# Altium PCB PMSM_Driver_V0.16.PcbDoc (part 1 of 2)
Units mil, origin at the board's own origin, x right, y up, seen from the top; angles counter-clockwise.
Board outline 3933.5 x 3936.3 mil, 2 copper layers (Top Layer, Bottom Layer); 174 components, 117 nets, 508 pads, 484 vias.
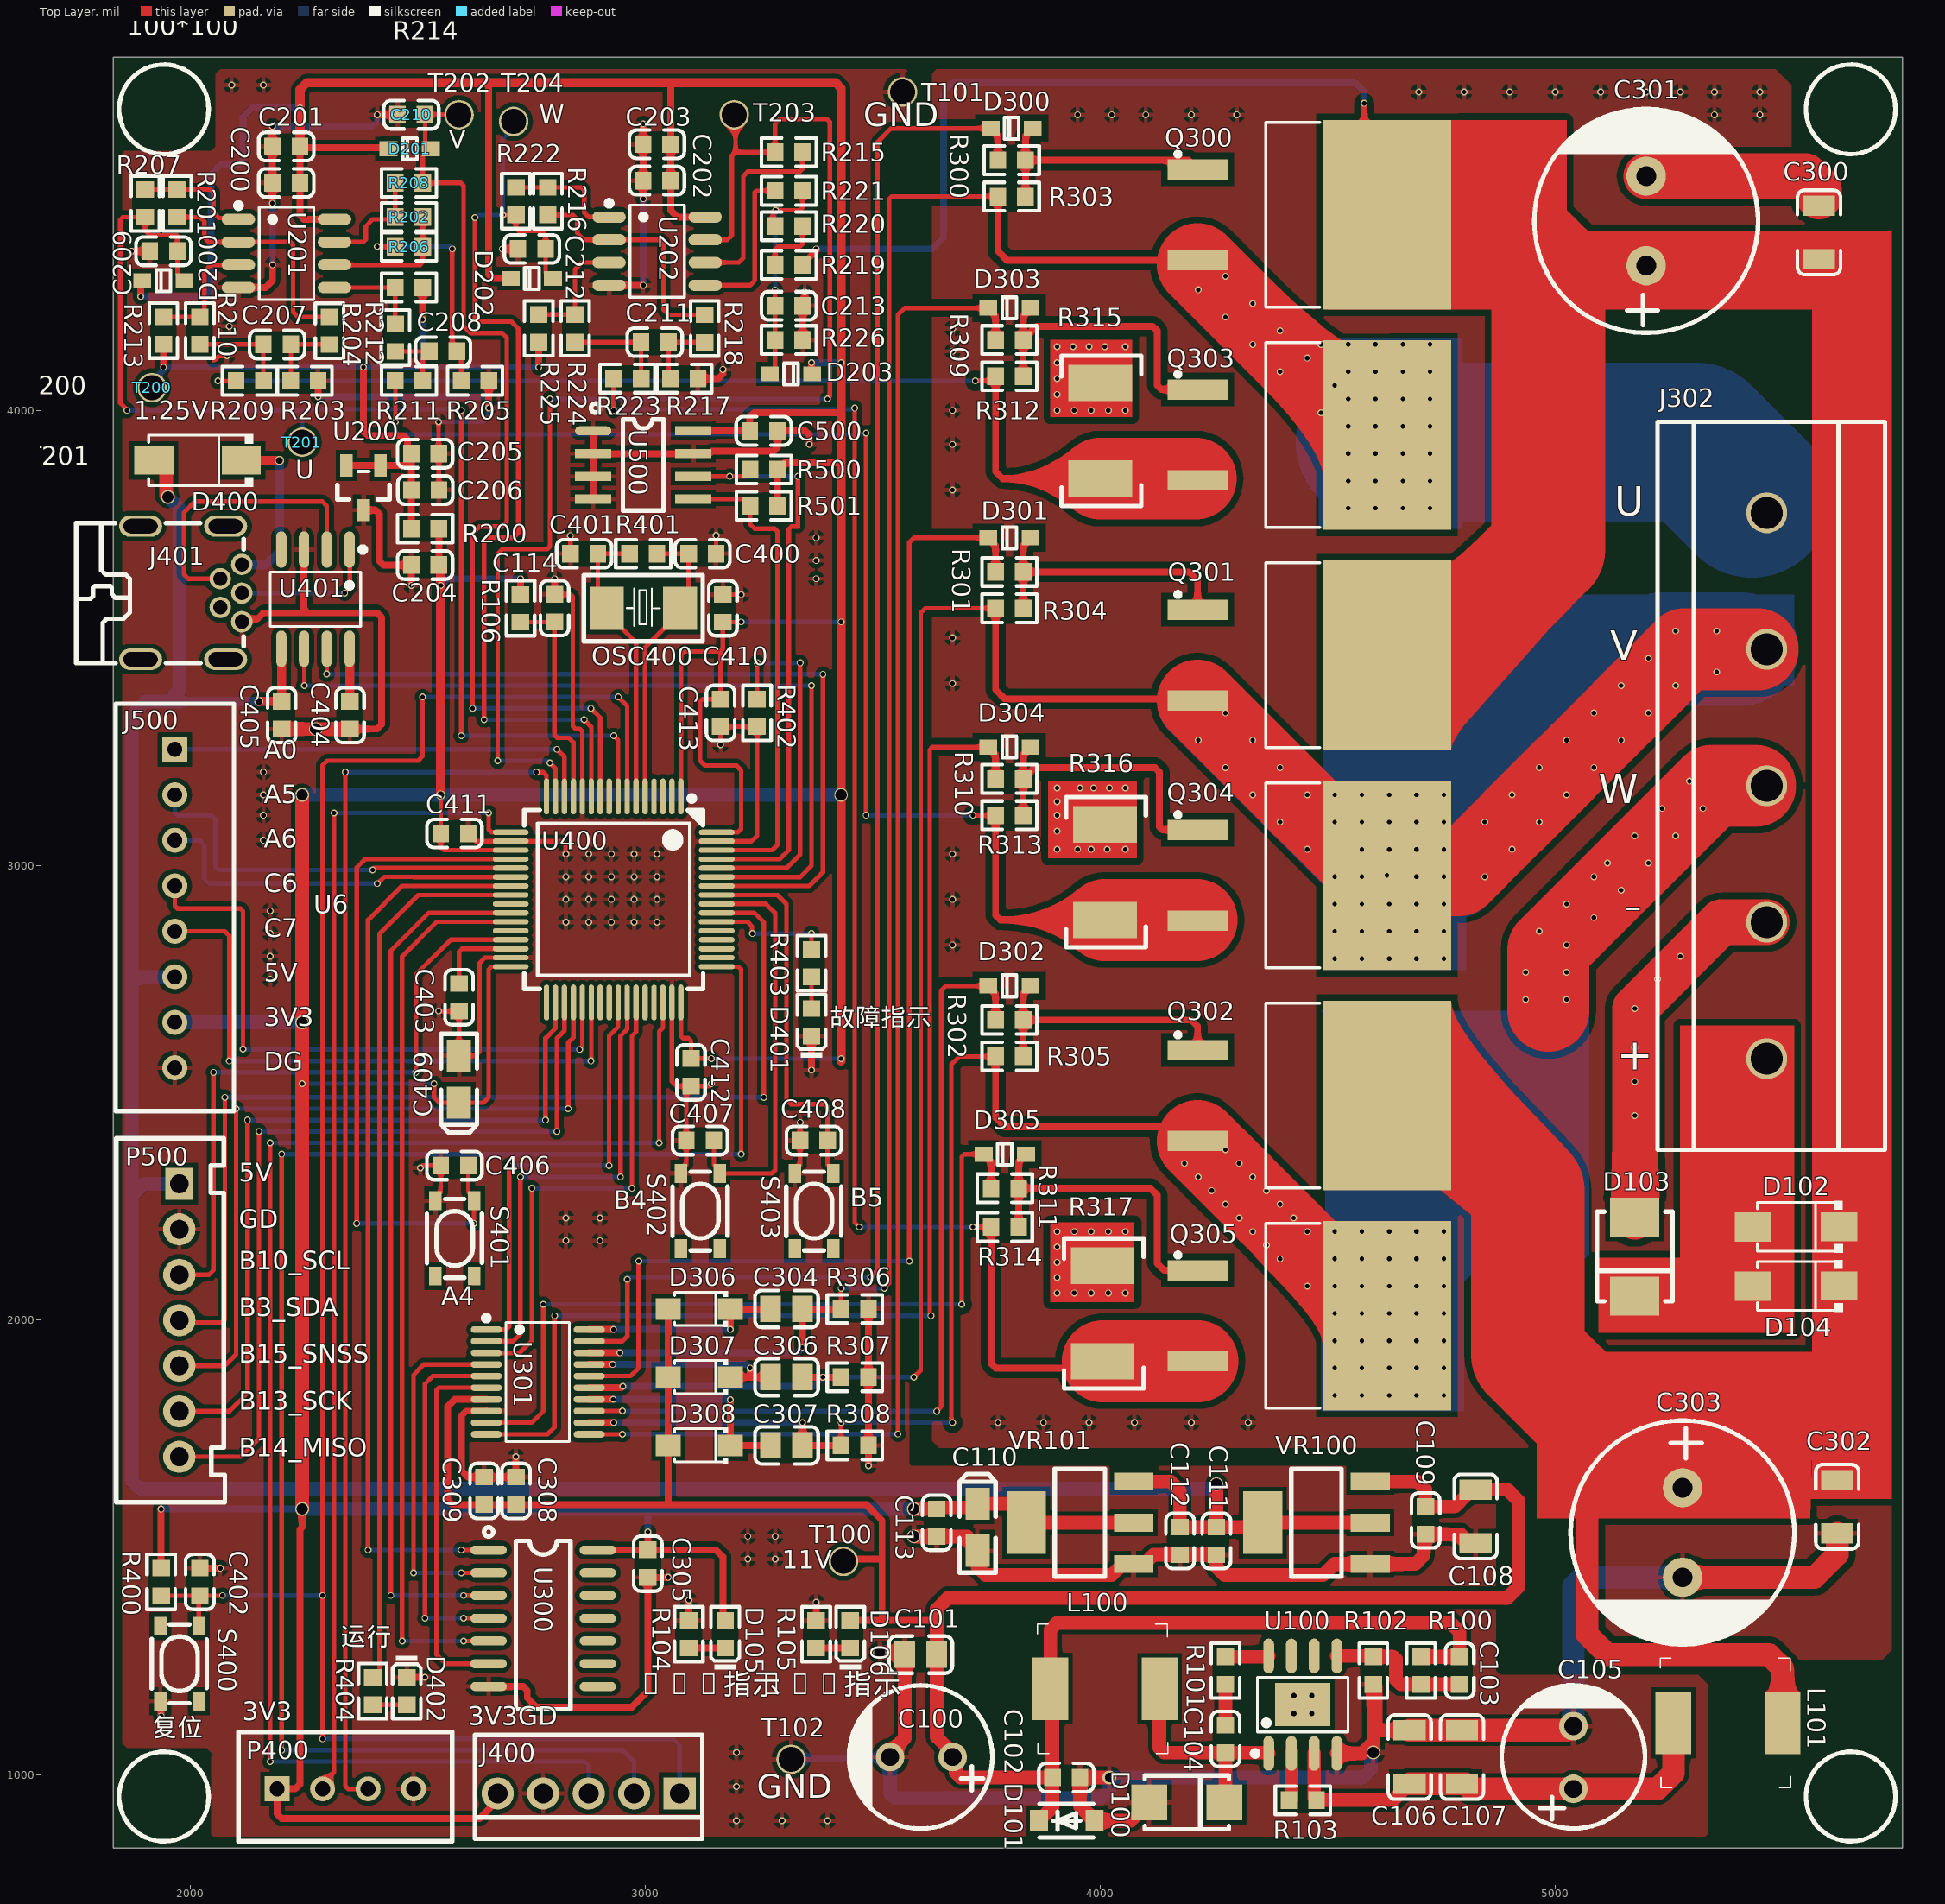
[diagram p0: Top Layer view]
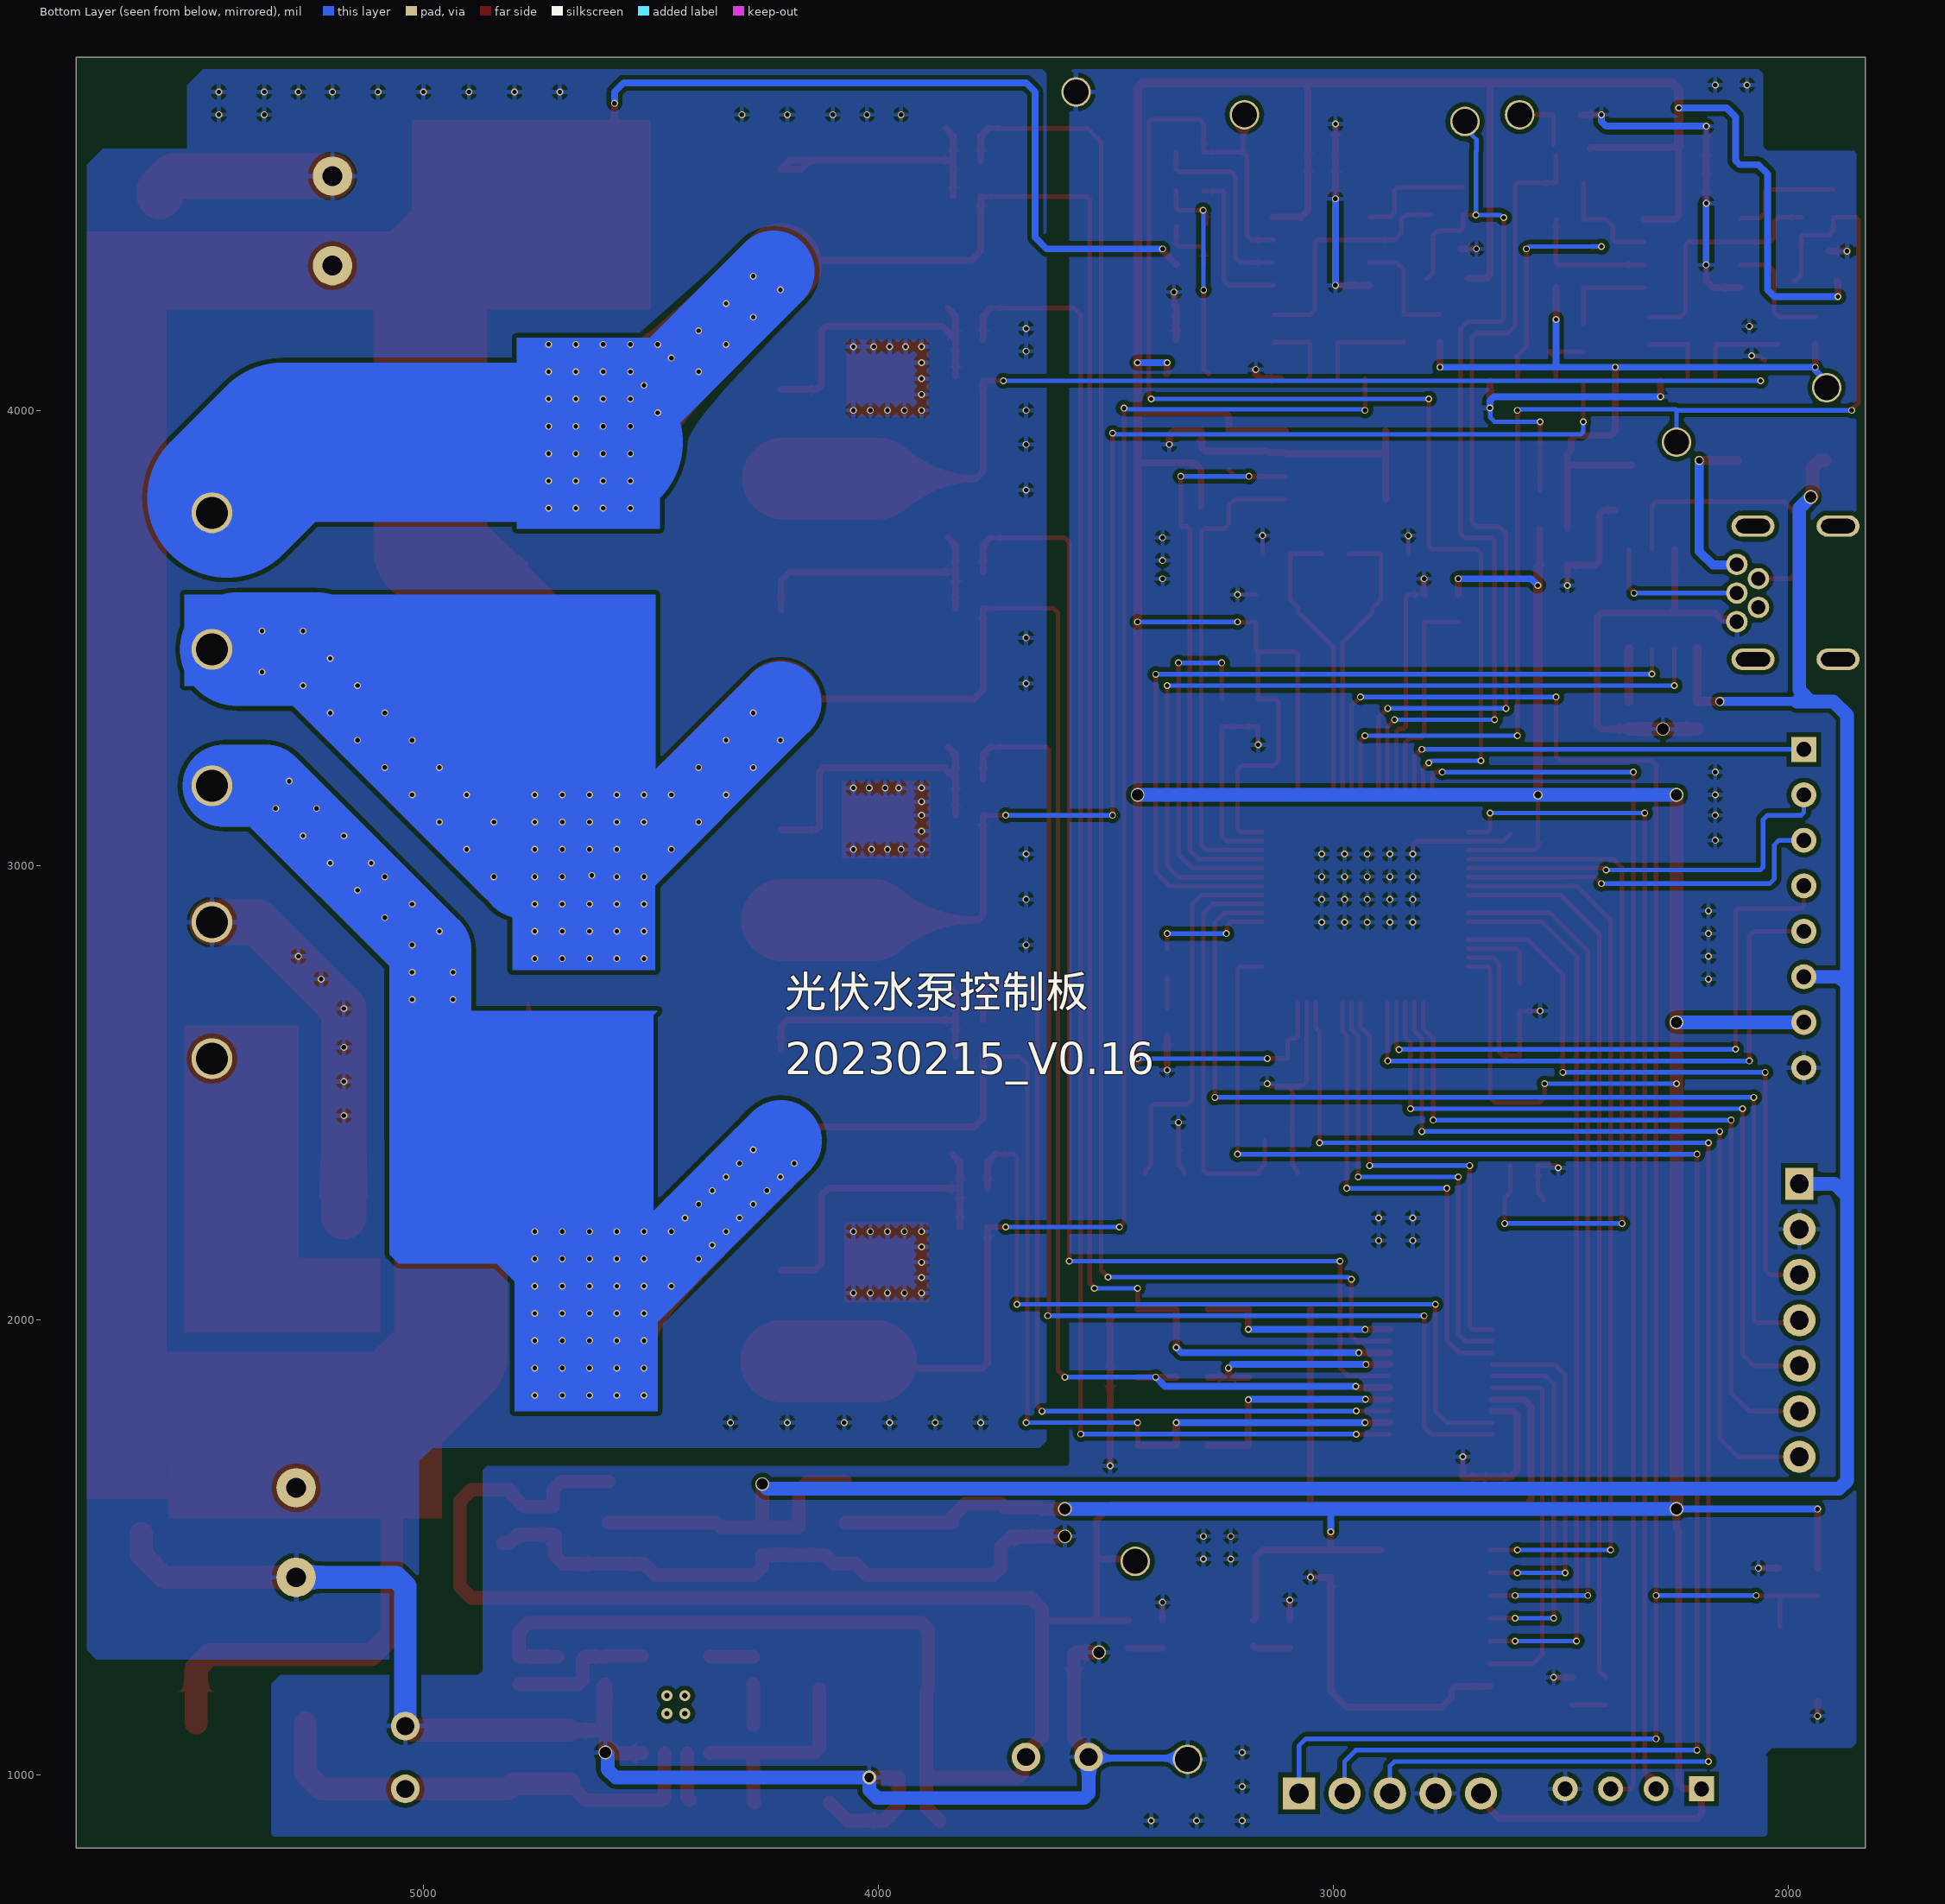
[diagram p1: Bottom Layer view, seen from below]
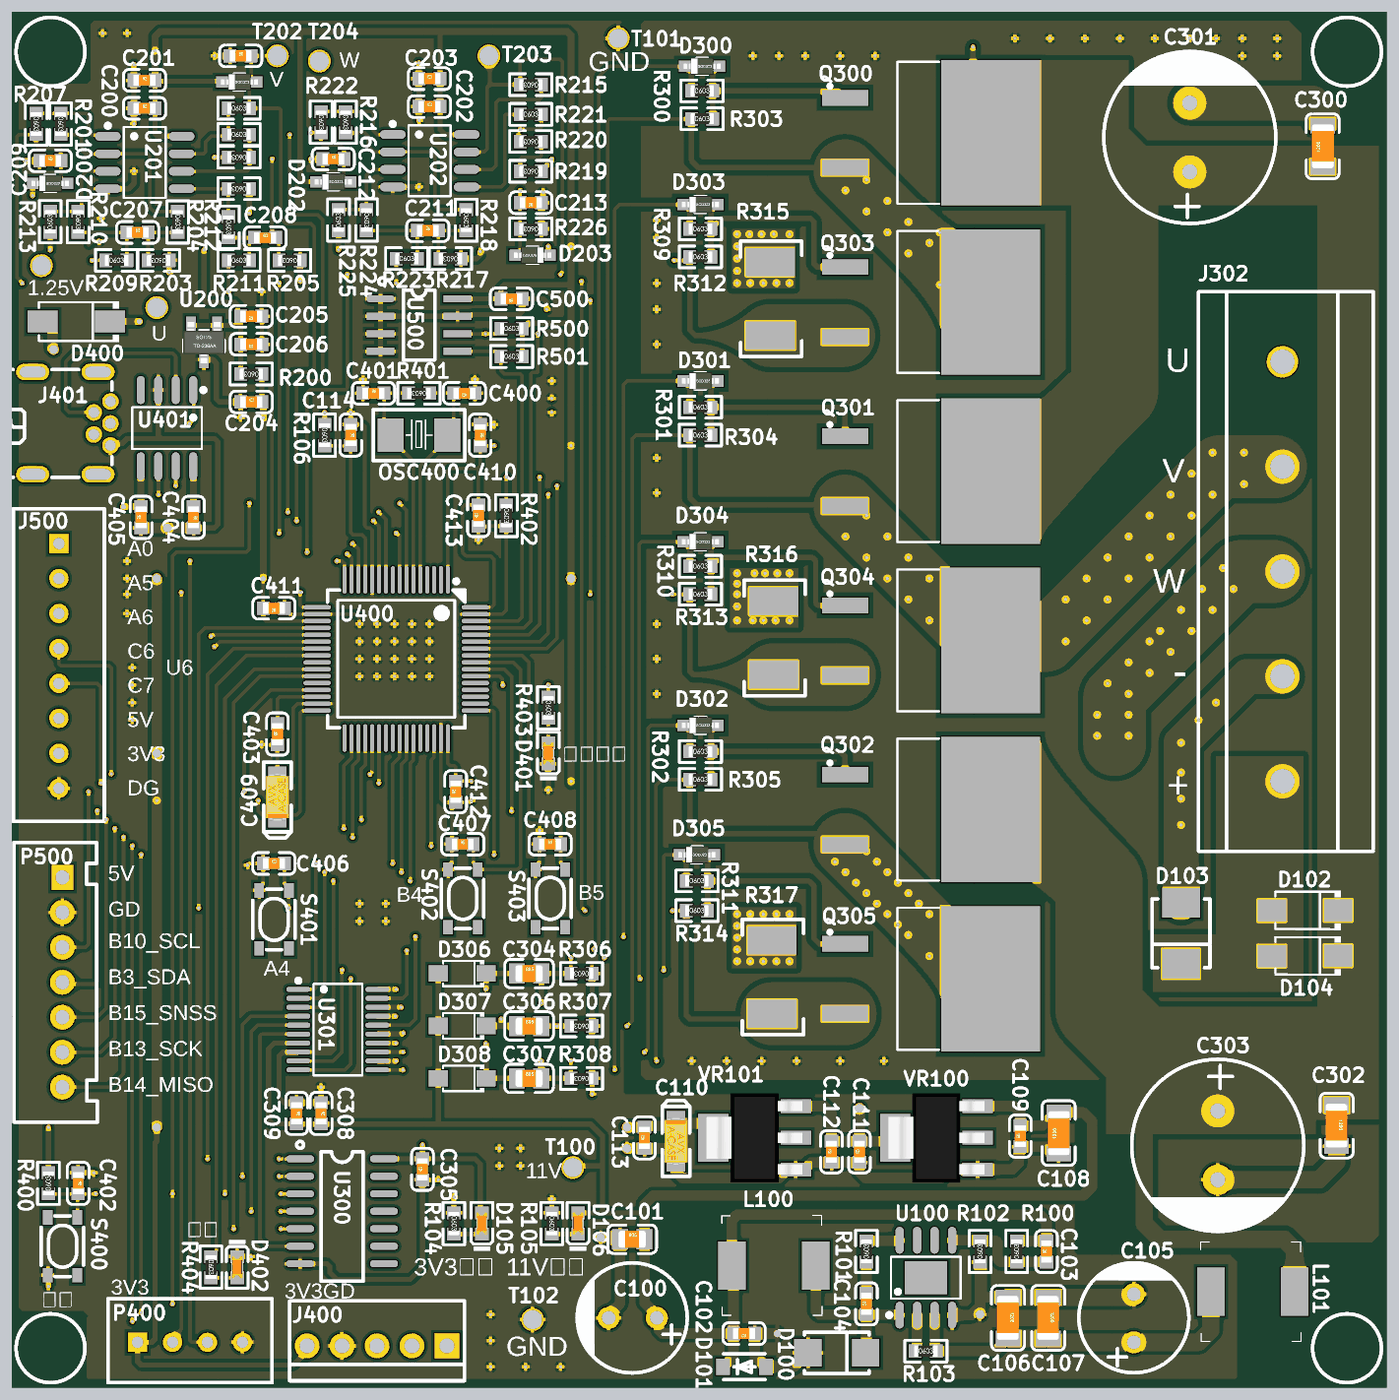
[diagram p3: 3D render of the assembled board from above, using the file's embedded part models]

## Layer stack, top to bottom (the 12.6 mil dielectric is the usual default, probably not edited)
Top Solder: solder mask 0.4, Solder Resist, Dk 3.5
Top Layer: signal copper 1.4
Dielectric 1: dielectric 12.6, FR-4, Dk 4.8
Bottom Layer: signal copper 1.4
Bottom Solder: solder mask 0.4, Solder Resist, Dk 3.5

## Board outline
1830,840 1830,4776.3 5763.5,4776.3 5763.5,840

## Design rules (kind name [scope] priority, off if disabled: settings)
Clearance [All] p1: gap=6 ignorepadtopadclearanceinfootprint=FALSE
ComponentClearance [All] p1: gap=0 collisioncheckmode=3 verticalgap=0 showdistances=FALSE
HoleToHoleClearance [All] p1: gap=0 allowstackedmicrovias=TRUE
MinimumSolderMaskSliver [All] p1: minsoldermaskwidth=0
PolygonConnect [All] p1: connectstyle=Relief reliefconductorwidth=10 reliefentries=4 polygonreliefangle="90 Angle" airgapwidth=10
RoutingVias [All] p1: holewidth=10 width=13 viastyle="Through Hole" minholewidth=10 minwidth=13 maxholewidth=50 maxwidth=50
SilkToSilkClearance [All] p1: silktosilkclearance=0
SilkToSolderMaskClearance [IsPad] p1: minsilkscreentomaskgap=0 clearancetoexposedcopper=TRUE
SolderMaskExpansion [All] p1: expansion=4 istentingtop=FALSE
Width [All] p1: maxlimit=500 minlimit=10 preferedwidth=10
25 further rules are at their usual default settings.

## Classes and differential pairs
component class 05_Peripheral: C500 J500 P500 R500 R501 U500
component class 04_Mcu: C400 C401 C402 C403 C404 C405 C406 C407 C408 C409 C410 C411 C412 C413 D400 D401 D402 J400 J401 OSC400 P400 R400 R401 R402 R403 R404 S400 S401 S402 S403 U400 U401
component class 03_MOS_Drive: C300 C301 C302 C303 C304 C305 C306 C307 C308 C309 D300 D301 D302 D303 D304 D305 D306 D307 D308 J302 Q300 Q301 Q302 Q303 Q304 Q305 R300 R301 R302 R303 R304 R305 R306 R307 R308 R309 R310 R311 R312 R313 R314 R315 R316 R317 U300 U301
component class 02_Sensor: C200 C201 C202 C203 C204 C205 C206 C207 C208 C209 C210 C211 C212 C213 D200 D201 D202 D203 R200 R201 R202 R203 R204 R205 R206 R207 R208 R209 R210 R211 R212 R213 R214 R215 R216 R217 R218 R219 R220 R221 R222 R223 R224 R225 R226 T200 T201 T202 T203 T204 U200 U201 U202
component class 01_Power: C100 C101 C102 C103 C104 C105 C106 C107 C108 C109 C110 C111 C112 C113 C114 D100 D101 D102 D103 D104 D105 D106 L100 L101 R100 R101 R102 R103 R104 R105 R106 T100 T101 T102 U100 VR100 VR101

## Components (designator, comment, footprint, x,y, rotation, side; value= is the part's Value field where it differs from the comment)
C100 "470uF/25V" 47UF/100V 3605,1040 r180 top
C101 "22uF (226) 20% 25V" LC-0805_C 3605,1265 r0 top
C102 "100nF (104) 10% 50V" LC-0603_C 3925,995 r180 top
C103 "47pF (470) 5% 50V" LC-0603_C 4790,1230 r90 top
C104 "100nF (104) 10% 50V" LC-0603_C 4275,1080 r90 top
C105 "47uF/100V" 47UF/100V 5039.97,1040.4 r90 top
C106 "2.2uF (225) 10% 100V" LC-1206_C 4680,1040 r270 top
C107 "100nF (104) 10% 100V" LC-1206_C 4795,1040 r270 top
C108 "10uF (106) 10% 50V" LC-1206_C 4825,1568.66 r90 top
C109 "100nF (104) 10% 50V" LC-0603_C 4715,1560 r90 top
C110 "10uF (106) ±10% 16V" LC-CASE-A_3216 3730,1545 r90 top
C111 "100nF (104) 10% 50V" LC-0603_C 4255,1515 r90 top
C112 "100nF (104) 10% 50V" LC-0603_C 4175,1515 r90 top
C113 "100nF (104) 10% 50V" LC-0603_C 3640,1555 r90 top
C114 "100nF (104) 10% 50V" LC-0603_C 2800,3565.32 r270 top
C200 "10uF (106) 10% 10V" LC-0603_C 2210,4500 r0 top
C201 "100nF (104) 10% 50V" LC-0603_C 2210,4580 r0 top
C202 "100nF (104) 10% 50V" LC-0603_C 3025,4505 r0 top
C203 "10uF (106) 10% 10V" LC-0603_C 3025,4585 r0 top
C204 "10uF (106) 10% 10V" LC-0603_C 2515.32,3660 r0 top
C205 "10uF (106) 10% 10V" LC-0603_C 2515.32,3905 r180 top
C206 "100nF (104) 10% 50V" LC-0603_C 2515.63,3825 r180 top
C207 "100pF (101) 5% 50V" LC-0603_C 2190,4145 r0 top
C208 "100pF (101) 5% 50V" LC-0603_C 2555,4130 r0 top
C209 "1nF (102) 10% 50V" LC-0603_C 1940.32,4350 r0 top
C210 "1nF (102) 10% 50V" LC-0603_C 2485,4650 r0 top
C211 "100pF (101) 5% 50V" LC-0603_C 3020.32,4150 r0 top
C212 "1nF (102) 10% 50V" LC-0603_C 2750,4355 r0 top
C213 "2.2uF (225) 10% 16V" LC-0603_C 3315,4230 r180 top
C300 "2.2uF (225) 10% 100V" LC-1206_C 5580,4391.34 r90 top
C301 "220uF/100V" 220UF/100V 5200,4318.15 r90 top
C302 "2.2uF (225) 10% 100V" LC-1206_C 5620,1590 r270 top
C303 "220uF/100V" 220UF/100V 5280,1631.85 r270 top
C304 "4.7uF (475) 10% 25V" LC-0805_C 3310,2025 r0 top
C305 "100nF (104) 10% 50V" LC-0603_C 3005,1465 r90 top
C306 "4.7uF (475) 10% 25V" LC-0805_C 3310,1875 r0 top
C307 "4.7uF (475) 10% 25V" LC-0805_C 3310,1725 r0 top
C308 "4.7uF (475) 10% 25V" LC-0603_C 2715,1625 r270 top
C309 "100nF (104) 10% 50V" LC-0603_C 2645,1625 r270 top
C400 "22pF (220) 5% 50V" LC-0603_C 3125,3685 r180 top
C401 "22pF (220) 5% 50V" LC-0603_C 2865,3685 r0 top
C402 "100nF (104) 10% 50V" LC-0603_C 2020,1425 r270 top
C403 "2.2uF (225) 10% 16V" LC-0603_C 2590,2710 r90 top
C404 "100nF (104) 10% 50V" LC-0603_C 2350,3330 r270 top
C405 "100nF (104) 10% 50V" LC-0603_C 2200,3330 r90 top
C406 "100nF (104) 10% 50V" LC-0603_C 2580,2340 r0 top
C407 "100nF (104) 10% 50V" LC-0603_C 3120,2395 r0 top
C408 "100nF (104) 10% 50V" LC-0603_C 3370,2395 r0 top
C409 "10uF (106) ±10% 16V" LC-CASE-A_3216 2590,2530 r270 top
C410 "100nF (104) 10% 50V" LC-0603_C 3170,3565 r270 top
C411 "100nF (104) 10% 50V" LC-0603_C 2580,3070 r180 top
C412 "100nF (104) 10% 50V" LC-0603_C 3100,2545 r90 top
C413 "100nF (104) 10% 50V" LC-0603_C 3165,3335 r90 top
C500 "100nF (104) 10% 50V" LC-0603_C 3259.68,3955 r180 top
D100 "SS310" LC-SMA(DO-214AC)_S1 4190,940 r180 top
D101 "SMF12A" "SMF12A - duplicate" 3865,900 r0 top
D102 "SS510" SS510 5624.29,2205.74 r180 top
D103 "SMAJ75CA" LC-SMB(DO-214AA)_S1 5175,2140 r90 top
D104 "SS510" SS510 5624.29,2075.74 r180 top
D105 "绿灯 0603" LC-0603_LED_S1 3175,1310 r90 top
D106 "绿灯 0603" LC-0603_LED_S1 3450,1310 r90 top
D200 "1N4148WS T4" LC-SOD-323 1940,4285 r0 top
D201 "1N4148WS T4" LC-SOD-323 2481.46,4575 r0 top
D202 "1N4148WS T4" LC-SOD-323 2750,4290 r0 top
D203 "1N4148WS T4" LC-SOD-323 3320,4080 r180 top
D300 "1N4148WS T4" LC-SOD-323 3805,4620 r0 top
D301 "1N4148WS T4" LC-SOD-323 3800,3720 r0 top
D302 "1N4148WS T4" LC-SOD-323 3800,2735 r0 top
D303 "1N4148WS T4" LC-SOD-323 3800,4225 r0 top
D304 "1N4148WS T4" LC-SOD-323 3800,3260 r0 top
D305 "1N4148WS T4" LC-SOD-323 3790,2365 r0 top
D306 "DSK110" DSK110 3186.61,2025 r180 top
D307 "DSK110" DSK110 3186.61,1875 r180 top
D308 "DSK110" DSK110 3186.61,1725 r180 top
D400 "SS54" SS54 2015,3890 r180 top
D401 "红灯 0603" LC-0603_LED_S1 3365,2655 r90 top
D402 "绿灯 0603" LC-0603_LED_S1 2475,1185 r270 top
J302 "CON5" "7.62-5P 端子" 5465,3775 r270 top locked
J400 "KF2510-5A" KF2510-5A 2870,974.17 r180 top
J401 "USB MINI" USB_MINI 2165.11,4623.34 r270 top
J500 "CON8" 2.54_8P_PHI 1965,3255 r270 top
L100 "47uH/0650" 0650_47uH 4000,1190 r180 top locked
L101 "47uH/0650" 0650_47uH 5370,1115 r180 top
OSC400 "8MHZ-5032" 8MHZ-5032 2995,3565 r180 top
P400 "Header 4" 2.54_4P_PIN 2190,970 r0 top
P500 "Header 7" XH2.54-7P 1975,2300 r270 top
Q300 "IRFS3607TRLPBF" TO-263-2 4322.68,4437 r0 top
Q301 "IRFS3607TRLPBF" TO-263-2 4322.68,3469 r0 top
Q302 "IRFS3607TRLPBF" TO-263-2 4322.68,2501 r0 top
Q303 "IRFS3607TRLPBF" TO-263-2 4322.68,3953 r0 top locked
Q304 "IRFS3607TRLPBF" TO-263-2 4322.68,2985 r0 top locked
Q305 "IRFS3607TRLPBF" TO-263-2 4322.68,2017 r0 top
R100 "301KΩ  ±1%" LC-0603_R 4705,1230 r90 top
R101 "22Ω (22R0) ±1%" LC-0603_R 4275,1230 r90 top
R102 "23.7KΩ (1502) ±1%" LC-0603_R 4600,1230 r90 top
R103 "30mΩ ±1%" LC-0603_R 4445,945 r0 top
R104 "10KΩ (1002) ±1%" LC-0603_R 3095,1310 r270 top
R105 "10KΩ (1002) ±1%" LC-0603_R 3375,1310 r270 top
R106 "0Ω (0R0) ±1%" LC-0603_R 2725,3565 r270 top
R200 "220Ω (2200) ±1%" LC-0603_R 2515.32,3740 r180 top
R201 "12KΩ (1202) ±1%" LC-0603_R 1970,4455 r270 top
R202 "12KΩ (1202) ±1%" LC-0603_R 2480,4425 r0 top
R203 "1KΩ (1001) ±1%" LC-0603_R 2250,4065 r180 top
R204 "1KΩ (1001) ±1%" LC-0603_R 2305,4175 r270 top
R205 "1KΩ (1001) ±1%" LC-0603_R 2625,4065 r180 top
R206 "1KΩ (1001) ±1%" LC-0603_R 2480,4360 r180 top
R207 "100Ω (1000) ±1%" LC-0603_R 1900,4455 r270 top
R208 "100Ω (1000) ±1%" LC-0603_R 2480,4500 r0 top
R209 "1KΩ (1001) ±1%" LC-0603_R 2130,4065 r0 top
R210 "1KΩ (1001) ±1%" LC-0603_R 2020,4175.31 r270 top
R211 "1KΩ (1001) ±1%" LC-0603_R 2480,4065 r0 top
R212 "1KΩ (1001) ±1%" LC-0603_R 2450,4160 r270 top
R213 "12KΩ (1202) ±1%" LC-0603_R 1940,4175.31 r90 top
R214 "12KΩ (1202) ±1%" LC-0603_R 2480,4270 r180 top
R215 "1KΩ (1001) ±1%" LC-0603_R 3315,4567.66 r180 top
R216 "12KΩ (1202) ±1%" LC-0603_R 2785,4460 r270 top
R217 "1KΩ (1001) ±1%" LC-0603_R 3085,4070 r180 top
R218 "1KΩ (1001) ±1%" LC-0603_R 3130,4180 r270 top
R219 "12KΩ (1202) ±1%" LC-0603_R 3315,4320 r180 top
R220 "12KΩ (1202) ±1%" LC-0603_R 3315,4405 r180 top
R221 "1KΩ (1001) ±1%" LC-0603_R 3315,4482.66 r0 top
R222 "100Ω (1000) ±1%" LC-0603_R 2715,4460 r270 top
R223 "1KΩ (1001) ±1%" LC-0603_R 2960,4070 r0 top
R224 "1KΩ (1001) ±1%" LC-0603_R 2845,4180.31 r270 top
R225 "12KΩ (1202) ±1%" LC-0603_R 2765,4180.31 r90 top
R226 "1KΩ (1001) ±1%" LC-0603_R 3315,4155 r180 top
R300 "22Ω (22R0) ±1%" LC-0603_R 3805,4550 r0 top
R301 "22Ω (22R0) ±1%" LC-0603_R 3800,3645 r0 top
R302 "22Ω (22R0) ±1%" LC-0603_R 3800,2660 r0 top
R303 "51KΩ (5102) ±1%" LC-0603_R 3805,4470 r0 top
R304 "51KΩ (5102) ±1%" LC-0603_R 3800,3565 r0 top
R305 "51KΩ (5102) ±1%" LC-0603_R 3800,2580 r0 top
R306 "20KΩ (2002) ±1%" LC-0603_R 3460,2025 r180 top
R307 "20KΩ (2002) ±1%" LC-0603_R 3460,1875 r180 top
R308 "20KΩ (2002) ±1%" LC-0603_R 3460,1725 r180 top
R309 "22Ω (22R0) ±1%" LC-0603_R 3800,4155 r0 top
R310 "22Ω (22R0) ±1%" LC-0603_R 3800,3190 r0 top
R311 "22Ω (22R0) ±1%" LC-0603_R 3790,2290 r0 top
R312 "51KΩ (5102) ±1%" LC-0603_R 3800,4075 r0 top
R313 "51KΩ (5102) ±1%" LC-0603_R 3800,3110 r0 top
R314 "51KΩ (5102) ±1%" LC-0603_R 3790,2205 r0 top
R315 "R02  0.02Ohm 1% 2512" R2512 3960,3930 r270 top
R316 "R02  0.02Ohm 1% 2512" R2512 3970,2960 r270 top
R317 "R02  0.02Ohm 1% 2512" R2512 3965,1990 r270 top
R400 "10KΩ (1002) ±1%" LC-0603_R 1935,1425 r90 top
R401 "1MΩ (1004) ±1%" LC-0603_R 2995,3685 r180 top
R402 "10KΩ (1002) ±1%" LC-0603_R 3245,3335 r270 top
R403 "10KΩ (1002) ±1%" LC-0603_R 3365,2785 r270 top
R404 "10KΩ (1002) ±1%" LC-0603_R 2400,1185 r270 top
R500 "10KΩ (1002) ±1%" LC-0603_R 3260,3870 r0 top
R501 "10KΩ (1002) ±1%" LC-0603_R 3260,3790 r0 top
S400 "KEY" KEY_WHITE 1975,1245 r270 top
S401 "KEY" KEY_WHITE 2580,2180 r270 top
S402 "KEY" KEY_WHITE 3120,2240 r270 top
S403 "KEY" KEY_WHITE 3370,2240 r270 top
T100 "Test" Testpoint 3435,1470 r90 top
T101 "Test" Testpoint 3565,4700 r90 top
T102 "Test" Testpoint 3320,1035 r90 top
T200 "Test" Testpoint 1915,4050 r90 top
T201 "Test" Testpoint 2245,3930 r90 top
T202 "Test" Testpoint 2590,4650 r90 top
T203 "Test" Testpoint 3195,4650 r90 top
T204 "Test" Testpoint 2710,4635 r90 top
U100 "TX4139" ESOP8 4370,1047.89 r0 top
U200 "ME432AXG" LC-SOT-23(SOT-23-3) 2380,3830 r90 top
U201 "LMV358" TP2412-SR 2105,4420 r270 top
U202 "LMV358" TP2412-SR 2920,4425 r270 top
U300 "74HC74" SOIC-14 2655,1495 r0 top
U301 "EG2133" TSSOP20 2725.39,1912.36 r270 top
U400 "STM32F401RET6" STM32F401RET6 2925,2930 r180 top
U401 "CH340N" CH340N 2270,3585 r180 top
U500 "AT24C256" SOIC8 2890,3955 r0 top
VR100 "AMS1117-5.0" LC-SOT-223 4475,1555 r0 top
VR101 "AMS1117-3.3" LC-SOT-223 3955,1555 r0 top

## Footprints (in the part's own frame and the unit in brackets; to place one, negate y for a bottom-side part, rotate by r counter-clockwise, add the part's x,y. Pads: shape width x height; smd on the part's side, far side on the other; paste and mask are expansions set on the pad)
2.54_4P_PIN [mil]
  rect 55x55 hole 33: 1(0,0)
  round 55 hole 33: 2(100,0) 3(200,0) 4(300,0)
  silkscreen extent -85,-115 385,125
2.54_8P_PHI [mil]
  rect 55x55 hole 33: 1(0,0)
  round 55 hole 33: 2(100,0) 3(200,0) 4(300,0) 5(400,0) 6(500,0) 7(600,0) 8(700,0)
  silkscreen extent -100,-130 795,130
"7.62-5P 端子" [mil]
  round 90 hole 70: 1(0,0) 2(300,0) 3(600,0) 4(900,0) 5(1200,0)
  silkscreen extent -200,-240 1400,260
8MHZ-5032 [mm]
  rect 1.9x2.4 smd: 1(-2.05,0) 2(2.05,0)
  silkscreen extent -3.32,-1.85 3.32,1.85
47UF/100V [mm]
  round 1.6 hole 1: 1(-1.788,-0.001) 2(1.712,-0.001)
  silkscreen extent -4,-4 4,4
220UF/100V [mm] "13*21"
  round 2.2 hole 1.1: 1(0,0) 2(5,0)
  silkscreen extent -3.75,-6.25 8.75,6.25
0650_47uH [mm]
  rect 2x3.5 smd: 1(-3.302,0) 2(2.794,0)
  silkscreen extent -3.76,-3.62 3.52,3.62
CH340N [mil]
  oval 22.6x80.14 smd: 1(-79.2,-108.97) 2(-29.2,-108.97) 3(20.8,-108.97) 4(70.8,-108.97) 5(70.8,108.97) 6(20.8,108.97) 7(-29.2,108.97) 8(-79.2,108.97)
  silkscreen extent -114,-115 95,60
DSK110 [mm] "SOD-123"
  rect 1.4x1.2 smd: 1(0,0) 2(3.47,0)
  silkscreen extent 0.13,-1 3.11,1
ESOP8 [mm]
  oval 0.602x1.941 smd: 1(0,0) 2(1.27,0) 3(2.54,0) 4(3.81,0) 5(3.81,5.441) 6(2.54,5.441) 7(1.27,5.441) 8(0,5.441)
  rect 3.098x2.41 smd: 9(1.905,2.72)
  silkscreen extent -0.9,-0.15 4.43,4.24
KEY_WHITE [mm]
  rect 1.05x0.7 smd: 1(-2.1,1.088) 2(2.1,1.088) 3(-2.1,-1.062) 4(2.1,-1.062)
  silkscreen extent -2.2,-1.54 2.2,1.54
KF2510-5A [mm]
  round 1.8 hole 1.1: 1(4.953,0.36) 2(2.413,0.36) 3(-0.127,0.36) 4(-2.667,0.36)
  rect 1.8x1.8 hole 1.1: 5(-5.207,0.36)
  silkscreen extent -6.48,-2.9 6.22,2.9
LC-0603_C [mm]
  rect 0.93x0.98 smd: 1(-0.77,0) 2(0.77,0)
  silkscreen extent -1.53,-0.79 1.54,0.79, body extent -0.8,-0.4 0.8,0.4, height 0.3
LC-0603_LED_S1 [mm]
  rect 0.93x0.98 smd: A(0.77,0) K(-0.77,0)
  silkscreen extent -1.98,-0.79 1.54,0.79, body extent -0.8,-0.4 0.8,0.4, height 0.6
LC-0603_R [mm]
  rect 0.93x0.98 smd: 1(-0.77,0) 2(0.77,0)
  silkscreen extent -1.53,-0.79 1.54,0.79, body extent -0.85,-0.4 0.85,0.4, height 0.56
LC-0805_C [mm]
  rect 1.16x1.47 smd: 1(-0.89,0) 2(0.89,0)
  silkscreen extent -1.77,-1.04 1.77,1.04, body extent -1,-0.62 1,0.63, height 0.77
LC-1206_C [mm]
  rect 1.13x1.8 smd: 1(-1.49,0) 2(1.49,0)
  silkscreen extent -2.36,-1.2 2.35,1.2, body extent -1.6,-0.81 1.6,0.79, height 1
LC-CASE-A_3216 [mm]
  rect 1.8x1.35 smd: 1(1.31,0) 2(-1.31,0)
  silkscreen extent -2.54,-1 2.97,1, body extent -1.7,-0.84 1.7,0.84, height 1.71
LC-SMA(DO-214AC)_S1 [mm]
  rect 2x2 smd: 1(2.1,0) 2(-2.1,0)
  silkscreen extent -2.35,-1.5 2.35,1.5
LC-SMB(DO-214AA)_S1 [mil]
  rect 85x107.99 smd: 1(87.01,0) 2(-87.01,0)
  silkscreen extent -98,-83 98,83
LC-SOD-323 [mm]
  rect 1x0.83 smd: 1(1.18,0) 2(-1.18,0)
  silkscreen extent -0.4,-0.6 0.4,0.6, body extent -1.35,-0.62 1.35,0.63, height 1.1
LC-SOT-23(SOT-23-3) [mm]
  rect 1.25x0.7 smd: 1(1.25,-0.95) 2(1.25,0.95) 3(-1.25,0)
  silkscreen extent -0.65,-1.46 0.9,1.46, body extent -1.5,-1.5 1.5,1.5, height 1.3
LC-SOT-223 [mm]
  rect 2.2x1 smd: 1(3,-2.3) 2(3,0) 3(3,2.3)
  rect 2.2x3.5 smd: 2(-3,0)
  silkscreen extent -1.4,-3 1.4,3, body extent -3.49,-3.24 3.49,3.24, height 1.64
R2512 [mil]
  rect 80x140 smd: 1(-130,40) 2(80,40)
  silkscreen extent -190,-45 140,130
"SMF12A - duplicate" [mm] "SOD123F"
  rect 1x1.2 smd: 1(0,0) 2(3.1,0)
  silkscreen extent 0.03,-0.93 3.04,0.95
SOIC8 [mil]
  oval 80x20 smd: 1(-5,0)
  rect 80x20 smd: 2(-5,-50) 3(-5,-100) 4(-5,-150) 5(215,-150) 6(215,-100) 7(215,-50) 8(215,0)
  silkscreen extent -10,-175 150,60
SOIC-14 [mil] "74HCXXX"
  oval 80x20 smd: 1(0,0) 2(0,-50) 3(0,-100) 4(0,-150) 5(0,-200) 6(0,-250) 7(0,-300) 8(240,-300) 9(240,-250) 10(240,-200) 11(240,-150) 12(240,-100) 13(240,-50) 14(240,0)
  silkscreen extent -10,-350 180,50
SS54 [mm]
  rect 2.185x1.593 smd: 1(-2.442,0) 2(2.442,0)
  silkscreen extent -3.11,-1.48 2.73,1.48
SS510 [mm]
  rect 2.046x1.62 smd: 1(0,0) 2(4.808,0.019)
  silkscreen extent -0.21,-1.43 4.57,1.45
STM32F401RET6 [mm]
  oval 0.3x2 smd: 1(-3.877,-5.623) 2(-3.377,-5.623) 3(-2.877,-5.623) 4(-2.377,-5.623) 5(-1.877,-5.623) 6(-1.377,-5.623) 7(-0.877,-5.623) 8(-0.377,-5.623) 9(0.123,-5.623) 10(0.623,-5.623) 11(1.123,-5.623) 12(1.623,-5.623) 13(2.123,-5.623) 14(2.623,-5.623) 15(3.123,-5.623) 16(3.623,-5.623) 33(3.623,5.877) 34(3.123,5.877) 35(2.623,5.877) 36(2.123,5.877) 37(1.623,5.877) 38(1.123,5.877) 39(0.623,5.877) 40(0.123,5.877) 41(-0.377,5.877) 42(-0.877,5.877) 43(-1.377,5.877) 44(-1.877,5.877) 45(-2.377,5.877) 46(-2.877,5.877) 47(-3.377,5.877) 48(-3.877,5.877)
  oval 2x0.3 smd: 17(5.623,-3.623) 18(5.623,-3.123) 19(5.623,-2.623) 20(5.623,-2.123) 21(5.623,-1.623) 22(5.623,-1.123) 23(5.623,-0.623) 24(5.623,-0.123) 25(5.623,0.377) 26(5.623,0.877) 27(5.623,1.377) 28(5.623,1.877) 29(5.623,2.377) 30(5.623,2.877) 31(5.623,3.377) 32(5.623,3.877) 49(-5.877,3.877) 50(-5.877,3.377) 51(-5.877,2.877) 52(-5.877,2.377) 53(-5.877,1.877) 54(-5.877,1.377) 55(-5.877,0.877) 56(-5.877,0.377) 57(-5.877,-0.123) 58(-5.877,-0.623) 59(-5.877,-1.123) 60(-5.877,-1.623) 61(-5.877,-2.123) 62(-5.877,-2.623) 63(-5.877,-3.123) 64(-5.877,-3.623)
  silkscreen extent -5.13,-5.66 4.87,5.13
Testpoint [mil]
  round 65 hole 55: 1(0,0)
TO-263-2 [mil]
  rect 132.23x44.65 smd: 1(-108.89,93) 3(-108.89,-107)
  rect 282.7x416 smd: 4(307.32,-7)
  silkscreen extent -157,-210 160,196
TP2412-SR [mm]
  oval 0.63x1.865 smd: 1(0,0) 2(1.27,0) 3(2.54,0) 4(3.81,0) 5(3.81,5.365) 6(2.54,5.365) 7(1.27,5.365) 8(0,5.365)
  silkscreen extent -0.92,-0.15 4.48,4.2
TSSOP20 [mil]
  oval 14.33x68.58 smd: 1(-67.36,-75.39) 2(-41.77,-75.39) 3(-16.18,-75.39) 4(9.41,-75.39) 5(35,-75.39) 6(60.59,-75.39) 7(86.18,-75.39) 8(111.77,-75.39) 9(137.36,-75.39) 10(162.95,-75.39) 11(162.95,150.67) 12(137.36,150.67) 13(111.77,150.67) 14(86.18,150.67) 15(60.59,150.67) 16(35,150.67) 17(9.41,150.67) 18(-16.18,150.67) 19(-41.77,150.67) 20(-67.36,150.67)
  silkscreen extent -98,-81 179,107
USB_MINI [mm]
  oval 1.2x2.4 hole 0.8 slot 1.9 at 90 deg: 0(22.291,-6.991) 0(22.291,-2.241) 0(29.731,-6.991) 0(29.731,-2.241)
  round 1.2 hole 0.8: 1(24.431,-1.339) 2(25.231,-2.543) 3(26.031,-1.339) 4(26.831,-2.543) 5(27.631,-1.339)
  silkscreen extent 22.12,-10.59 29.94,-1.24
XH2.54-7P [mm]
  rect 1.8x1.575 hole 1 slot 1.05 at 0 deg: 1(0,0)
  round 1.8 hole 1 slot 1.05 at 0 deg: 2(2.54,0) 3(5.08,0) 4(7.62,0) 5(10.16,0) 6(12.7,0) 7(15.24,0)
  silkscreen extent -2.54,-3.52 17.78,2.54

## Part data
C100 C105 C301 C303: library part CapSMT220u_16V
C101: library part "0805 22uF (226) 20% 25V", "贴片电容", Package=0805, SuppliersPartNumber=C45783
C102 C104 C109 C111 C112 C113 C114 C201 C202 C206 C305 C309 C402 C404 C405 C406 C407 C408 C410 C411 C412 C413 C500: library part "0603 100nF (104) 10% 50V", "贴片电容", Package=0603, SuppliersPartNumber=C14663
C103: library part "0603 47pF (470) 5% 50V", "贴片电容", Package=0603, SuppliersPartNumber=C1671
C106 C300 C302: library part "1206 2.2uF (225) 10% 50V", "贴片电容", Package=1206, SuppliersPartNumber=C12656
C107: library part "1206 100nF (104) 10% 50V", "贴片电容", Package=1206, SuppliersPartNumber=C24497
C108: library part "1206 10uF (106) 10% 50V", "贴片电容", Package=1206, SuppliersPartNumber=C13585
C110 C409: library part "3216 10uF (106) 10% 16V", "钽电容", Package=3216, SuppliersPartNumber=C7171
C200 C203 C204 C205: library part "0603 10uF (106) 10% 10V", "贴片电容", Package=0603, SuppliersPartNumber=C19702
C207 C208 C211: library part "0603 100pF (101) 5% 50V", "贴片电容", Package=0603, SuppliersPartNumber=C14858
C209 C210 C212: library part "0603 1nF (102) 10% 50V", "贴片电容", Package=0603, SuppliersPartNumber=C1588
C213 C403: library part "0603 2.2uF (225) 10% 16V", "贴片电容", Package=0603, SuppliersPartNumber=C23630
C304 C306 C307: library part "0805 4.7uF (475) 10% 25V", "贴片电容", Package=0805, SuppliersPartNumber=C1779
C308: library part "0603 4.7uF (475) 10% 16V", "贴片电容", Package=0603, SuppliersPartNumber=C19666
C400 C401: library part "0603 22pF (220) 5% 50V", "贴片电容", Package=0603, SuppliersPartNumber=C1653
D100 D306 D307 D308 D400: library part "SMA(DO-214AC) SS54", "二极管", Package=SMA(DO-214AC), SuppliersPartNumber=C22452
D103: library part "SMB/DO-214AA P6SMB6.8CA", "TVS", Package=SMB/DO-214AA, SuppliersPartNumber=C78395
D105 D106 D402: library part "0603 绿灯", "发光二极管", Package=0603, SuppliersPartNumber=C72043
D200 D201 D202 D203 D300 D301 D302 D303 D304 D305: library part "SOD-323 1N4148WS T4", "二极管", Package=SOD-323, SuppliersPartNumber=C2128
D401: library part "0603 红灯", "发光二极管", Package=0603, SuppliersPartNumber=C2286
L100 L101: library part Inductor
P400: "Header, 4-Pin"
P500: "Header, 7-Pin"
R100: library part "0603 330KΩ (3303) 1%", "贴片电阻", Package=0603, SuppliersPartNumber=C23137
R101 R300 R301 R302 R309 R310 R311: library part "0603 22Ω (22R0) 1%", "贴片电阻", Package=0603, SuppliersPartNumber=C23345
R102: library part "0603 15KΩ (1502) 1%", "贴片电阻", Package=0603, SuppliersPartNumber=C22809
R103: library part "0603 100KΩ (1003) 1%", "贴片电阻", Package=0603, SuppliersPartNumber=C25803
R104 R105 R400 R402 R403 R404 R500 R501: library part "0603 10KΩ (1002) 1%", "贴片电阻", Package=0603, SuppliersPartNumber=C25804
R106: library part "0603 0Ω (0R0) 1%", "贴片电阻", Package=0603, SuppliersPartNumber=C21189
R200: library part "0603 220Ω (2200) 1%", "贴片电阻", Package=0603, SuppliersPartNumber=C22962
R201 R202 R213 R214 R216 R219 R220 R225: library part "0603 12KΩ (1202) 1%", "贴片电阻", Package=0603, SuppliersPartNumber=C22790
R203 R204 R205 R206 R209 R210 R211 R212 R215 R217 R218 R221 R223 R224 R226: library part "0603 1KΩ (1001) 1%", "贴片电阻", Package=0603, SuppliersPartNumber=C21190
R207 R208 R222: library part "0603 100Ω (1000) 1%", "贴片电阻", Package=0603, SuppliersPartNumber=C22775
R303 R304 R305 R312 R313 R314: library part "0603 51KΩ (5102) 1%", "贴片电阻", Package=0603, SuppliersPartNumber=C23196
R306 R307 R308: library part "0603 20KΩ (2002) 1%", "贴片电阻", Package=0603, SuppliersPartNumber=C4184
R315 R316 R317: library part Res10K
R401: library part "0603 1MΩ (1004) 1%", "贴片电阻", Package=0603, SuppliersPartNumber=C22935
S400 S401 S402 S403: "白色方块"
T100 T101 T102 T200 T201 T202 T203 T204: library part TestPad
U200: library part "CJ431 0.5%431", "电压基准", Package=SOT-23, SuppliersPartNumber=C3113
U201 U202: library part LM358DR2G, "通用运放", Package=SOIC-8, SuppliersPartNumber=C7950
U300: library part 74HC14
VR100: library part "SOT-223 AMS1117-5.0", "低压差线性稳压(LDO)", Package=SOT-223, SuppliersPartNumber=C6187
VR101: library part "SOT-223 AMS1117-3.3", "低压差线性稳压(LDO)", Package=SOT-223, SuppliersPartNumber=C6186

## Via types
v1: diameter 15, hole 10, Top Layer to Bottom Layer, 465 vias
v2: diameter 30, hole 25, Top Layer to Bottom Layer, 11 vias
v3: diameter 24, hole 12, Top Layer to Bottom Layer, 4 vias
v4: diameter 20, hole 15, Top Layer to Bottom Layer, 3 vias
v5: diameter 30, hole 20, Top Layer to Bottom Layer, 1 vias

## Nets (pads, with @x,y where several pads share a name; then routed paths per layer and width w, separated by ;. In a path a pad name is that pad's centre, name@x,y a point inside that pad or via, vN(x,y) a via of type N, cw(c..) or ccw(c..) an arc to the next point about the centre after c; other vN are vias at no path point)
3V3DD: C110.1 C113.2 C200.2 C201.2 C202.2 C203.2 C204.2 C305.2 C409.1 C410.2 C411.2 C412.2 C413.2 C500.2 D105.A D200.2 D201.2 D202.2 D203.2 J400.1 J500.7 P400.1 R106.1 R200.1 R400.2 R500.2 R501.2 U201.8 U202.8 U300.14 U400.1 U400.19 U400.32 U400.48 U400.64 U500.8 VR101.2 | length 16876.5
  Top Layer w10: v1(2535,2520) 2535,2490 2546.57,2478.43 C409.1@2590,2478.43 2643.43,2478.43 2655,2490 2655,2771.16 2660.86,2777.01 2703.28,2777.01 U400.32@2703.63,2777.36 ; v4(2549.68,3154.68) C411.2@2549.68,3070 2549.68,3040.32 2556.73,3033.27 U400.19@2703.63,3033.27 ; U400.48@3077.64,2698.63 3077.64,2625 3082.64,2620 3094.14,2620 3100,2614.14 C412.2@3100,2575.32 v1(3144.68,2575.32) v1@3145,2575 ; U400.1@3077.64,3151.37 3077.64,3462.64 3085,3470 3164.14,3470 ; U400.64@3156.37,3072.64 3156.72,3072.99 3202.99,3072.99 3210,3080 3210,3210 3209.46,3210 3200,3219.46 3130.54,3219.46 3120,3230 3120,3359.46 3125.86,3365.32 C413.2@3165,3365.32 3165,3469.14 3164.14,3470 ; v1(3210,3535) 3209.68,3534.68 C410.2@3170,3534.68 3170,3475.86 3164.14,3470
  Top Layer w15: v1(1890,4250) 1890,4281.46 D200.2@1893.54,4285 ; R400.2@1935,1455.32 v1(1935,1585) ; v2(2245,1585) 2245,1545 2240,1540 2240,980 2230,970 P400.1@2190,970 2190,915 2200,905 2635,905 2675,945 J400.1@2675,960 ; U201.8@2316.22,4420 2248.79,4420 2240,4428.79 2240,4514.69 2240.32,4515 C201.2@2240.32,4580 2242.82,4577.5 2432.5,4577.5 D201.2@2435,4575 ; C204.2@2545.63,3660 R200.1@2545.63,3740 ; 2655,4720 2655,4298.79 2663.79,4290 D202.2@2703.54,4290 ; R106.1@2725,3595.31 v1(2725,3630) ; U300.14@2895,1495 2895.16,1495.16 3004.84,1495.16 C305.2@3005,1495.32 ; v1(3005,1535) C305.2@3005,1495.32 ; 3055,4720 3055.32,4719.69 C203.2@3055.32,4585 C202.2@3055.32,4505 3055.32,4439.68 3065.01,4429.99 3070,4425 U202.8@3131.22,4425 ; U500.8@3105,3955 C500.2@3229.37,3955 3229.37,3986.21 3238.16,3995 3425,3995 3430,4000 ; D105.A@3175,1340.32 3170,1345.32 3170,1480 3154.68,1495.32 C305.2@3005,1495.32 ; R501.2@3290.32,3790 R500.2@3290.32,3870 3290.32,3870.98 3301.12,3881.79 3302.11,3881.79 3305.32,3885 3430,3885 ; v1(3365,4105) 3365,4081.46 D203.2@3366.46,4080
  Top Layer w20: C201.2@2240.32,4580 2240.32,4665 2240.32,4705.31 2255,4720 2655,4720 3055,4720 3418.28,4720 3430,4708.28 v1(3430,4105) 3430,4000 3430,3885 v1(3430,3535) v2(3430,3155) v1(3430,2575) v1@3430,2570 ; C204.2@2545.63,3660 2549.68,3655.95 v4(2549.68,3154.68)
  Top Layer w30: v2(2245,1585) v1(2245,2520) v2(2245,3155) ; v2(3590,1585) 3590.32,1585.32 C113.2@3640,1585.32 3643.31,1588.62 3722.05,1588.62 C110.1@3730,1596.57 3808.58,1596.57 3836.89,1568.27 VR101.2@3836.89,1555 VR101.2@4073.11,1555
  Bottom Layer w10: v1(2245,2520) v1(2535,2520) ; v1(3144.68,2575.32) 3145,2575 v1(3430,2575) ; v1(3210,3535) v1(3430,3535)
  Bottom Layer w15: v1(1890,4250) 2030,4250 2045,4265 2045,4520 2065,4540 2106.21,4540 2115,4548.79 2115,4645 2135,4665 v1(2240,4665) ; v1(1935,1585) v2(2245,1585) ; v1(2550,3615) 2565,3630 v1(2725,3630) ; v1(3005,1535) 3005,1580 3010,1585 ; v1(3365,4105) v1(3430,4105)
  Bottom Layer w30: J500.7@1965,2655 v2(2245,2655) ; v2(2245,1585) 3010,1585 v2(3590,1585) ; v2(2245,3155) v2(3430,3155)
3V3DDA: C114.2 R106.2 U400.13 | length 491.3
  Top Layer w10: R106.2@2725,3534.68 R106.2@2740,3534.68 ; R106.2@2740.32,3535 R106.2@2740,3534.68 ; U400.13@2841.42,3151.37 2841.42,3270 2831.42,3280 2805.86,3280 2800,3285.86 C114.2@2800,3535 2799.68,3534.68 R106.2@2740,3534.68
5VDD: C111.2 C112.2 C405.2 D400.2 J500.6 P500.1 U401.5 VR100.2 VR101.3 | length 6033.2
  Top Layer w20: v4(2150,3360) 2150.32,3360.32 C405.2@2200,3360.32 2199.6,3360.71 2199.6,3475.63 U401.5@2199.2,3476.03
  Top Layer w30: D400.2@1918.84,3890 1930,3890 1946.36,3873.64 1946.36,3813.64 v2(1950,3810) ; VR101.3@4073.11,1645.55 4154.45,1645.55 4175,1625 C112.2@4175,1545.32 C111.2@4255,1545.32 ; v2(4255,1640) C111.2@4255,1545.32 ; VR100.2@4593.11,1555 VR100.2@4356.89,1555 4347.2,1545.32 C111.2@4255,1545.32
  Bottom Layer w20: 1980,3360 v4(2150,3360)
  Bottom Layer w30: v2(1950,3810) 1975,3785 1975,3385 1950,3360 ; J500.6@1965,2755 1887.57,2755 1870,2737.43 ; P500.1@1975,2300 1897.57,2300 1870,2272.43 ; 1980,3360 1950,3360 ; v2(4255,1640) 4245,1630 1887.57,1630 1870,1647.57 1870,2272.43 ; 1870,2272.43 1870,2737.43 ; 1870,2737.43 1870,3330 1900,3360 1950,3360
11VDD: C100.1 C101.2 C102.2 C103.2 C108.2 C109.2 C308.2 C309.2 D101.1 D106.A D306.2 D307.2 D308.2 L100.2 R100.2 T100.1 U301.7 VR100.3 | length 6172
  Top Layer w15: U301.7@2650,1826.18 2581.18,1826.18 2565,1810 2565,1605 2575,1595 2644.68,1595 C309.2@2645,1594.68 C308.2@2715,1594.68 3050,1594.68 ; D306.2@3050,2025 D307.2@3050,1875 D308.2@3050,1725 3050,1594.68 ; T100.1@3435,1470 3440,1475 3520,1475 ; D106.A@3450,1340.32 3520,1340.32 ; 3640.04,1350 3630.35,1340.32 3520,1340.32 ; 3050,1594.68 3485.32,1594.68 3520,1560 3520,1475 ; 3520,1340.32 3520,1475
  Top Layer w30: D101.1@3865,900 3894.68,929.68 C102.2@3894.68,995 ; VR100.3@4593.11,1645.55 4697.43,1645.55 4715,1627.98 C109.2@4715,1590.32 4779.29,1590.32 4804.57,1615.59 4804.57,1620.08 4811.81,1627.32 C108.2@4825,1627.32 4895.1,1627.32 4920,1602.43 4920,1415 4895,1390 3665,1390 3640.04,1365.04 3640.04,1350 C101.2@3640.04,1265 3640.04,1084.31 3675.4,1048.95 C100.1@3675.4,1040.03 3681.71,1033.71 3681.71,1005.86 3692.57,995 C102.2@3894.68,995 ; R100.2@4705,1260.32 C103.2@4790,1260.32 4790,1315 4770,1335 3905,1335 3890,1320 L100.2@3890,1190 3894.68,1185.32 C102.2@3894.68,995
75V-PVDC: D102.2 D103.2 D104.2 J302.5
DGND: C100.2 C101.1 C102.1 C105.2 C106.1 C107.1 C108.1 C109.1 C110.2 C111.1 C112.1 C113.1 C114.1 C200.1 C201.1 C202.1 C203.1 C204.1 C205.1 C206.1 C209.1 C210.1 C212.1 C213.1 C300.2 C301.2 C302.2 C303.2 C305.1 C308.1 C309.1 C400.1 C401.1 C402.1 C403.1 C404.2 C405.1 C406.1 C407.1 C408.1 C409.2 C410.1 C411.1 C412.1 C413.1 C500.1 D100.1 D101.2 D103.1 D401.K D402.K J302.4 J400.2 J401.5 J500.8 P400.4 P500.2 R102.1 R104.1 R105.1 R203.1 R205.1 R217.1 R226.1 R306.1 R307.1 R308.1 R315.1 R316.1 R317.1 R402.2 S400.4 S401.3 S402.3 S403.3 T101.1 T102.1 U100.4 U200.3 U201.4 U202.4 U300.7 U301.8 U400.12 U400.18 U400.31 U400.47 U400.63 U401.3 U500.1 U500.2 U500.3 U500.4 U500.7 VR100.1 VR101.1 | length 14688.1
  Top Layer w10: 2050.44,4109.56 2052.58,4111.69 2054.29,4111.69 2061.64,4119.04 2079.04,4119.04 v1(2080,4120) ; v1(2505,2335) 2510,2340 C406.1@2549.68,2340 2549.68,2281.07 2538.18,2269.57 S401.3@2538.18,2262.68 ; v1(2545,2680) 2545.32,2679.68 C403.1@2590,2679.68 C409.2@2590,2581.57 2626.57,2581.57 2635,2590 2635,2785 2647.05,2797.05 U400.31@2703.63,2797.05 ; v1(2545,3975) 2545,3905.63 C205.1@2545.63,3905 2545.63,3825.32 C206.1@2545.95,3825 ; C411.1@2610.32,3070 2610.32,3069.02 2626.38,3052.95 U400.18@2703.63,3052.95 2817.05,3052.95 2819.98,3050.02 2824.04,3045.96 2824.04,3025.96 v1(2825,3025) ; C114.1@2815,3595.63 2815.63,3595 2835.32,3595 2840,3590.32 2840,3306.1 2846.1,3300 2855.24,3300 2861.1,3294.14 U400.12@2861.1,3151.37 ; C401.1@2834.68,3685 v1(2834.68,3724.68) v1@2835,3725 ; U400.47@3057.95,2698.63 3057.95,2525 3068.26,2514.68 C412.1@3100,2514.68 ; S402.3@3078.18,2322.68 3078.18,2329.57 3089.68,2341.07 C407.1@3089.68,2395 3089.68,2504.37 C412.1@3100,2514.68 ; v1(3145,2520) 3139.68,2514.68 C412.1@3100,2514.68 ; v1(3155,3725) 3155.32,3724.68 C400.1@3155.32,3685 ; U400.63@3156.37,3052.95 3232.95,3052.95 3245,3065 R402.2@3245,3304.68 C413.1@3165,3304.68 v1(3165,3265) ; C410.1@3170,3595.32 3209.68,3595.32 v1(3210,3595) ; S403.3@3328.18,2322.68 3328.18,2329.57 3339.68,2341.07 C408.1@3339.68,2395 3339.68,2434.68 v1(3340,2435)
  Top Layer w15: v1(1870,4350) C209.1@1910,4350 ; S400.4@1933.18,1162.32 1935,1160.5 v1(1935,1130) ; C402.1@2020,1455.32 2064.68,1455.32 v1(2065,1455) ; U201.4@2105,4270 2165,4270 2180,4285 v1(2180,4320) ; J401.5@2112.39,3535.51 2118.56,3541.68 2146.68,3541.68 2160,3555 2257.99,3555 ; v1@2180,4455 v1(2179.68,4455.31) C200.1@2179.68,4500 C201.1@2179.68,4580 v1(2179.68,4624.69) v1@2180,4625 ; U401.3@2249.2,3693.97 2249.2,3563.79 2257.99,3555 ; v1@2280,4030 v1(2280.31,4030.31) R203.1@2280.31,4065 ; C404.2@2350,3299.68 2409.68,3299.68 2420,3310 2420,3545 2414.99,3550.01 2410,3555 2257.99,3555 ; U200.3@2380,3780.79 2406.21,3780.79 2415,3772 2415,3668.79 2423.79,3660 C204.1@2485,3660 v1(2485,3615) ; v1(2410,4650) C210.1@2454.68,4650 ; D402.K@2475,1215.31 2514.69,1215.31 v1(2515,1215) ; U301.8@2650,1800.59 2649.67,1800.26 2605.26,1800.26 2595,1790 2595,1670 2609.68,1655.32 C309.1@2645,1655.32 C308.1@2715,1655.32 v1(2715,1700) ; U300.7@2655,1195 2731.21,1195 2740,1186.21 2740,1170 2760,1150 2970,1150 3005,1185 C305.1@3005,1434.68 3049.68,1434.68 v1(3050,1435) ; v1@2655,4005 v1(2655.31,4005.31) R205.1@2655.31,4065 ; v1(2685,4355) C212.1@2719.68,4355 ; C114.1@2800,3595.63 v1(2800,3630) ; U500.4@2885,3805 U500.3@2885,3855 U500.2@2885,3905 ; U500.1@2885,3955 U500.2@2885,3905 ; U202.4@2920,4275 v1(2995,4275) ; v1(2995,4465) 2994.68,4465.31 C202.1@2994.68,4505 C203.1@2994.68,4585 v1(2994.68,4629.69) v1@2995,4630 ; R104.1@3095,1340.31 v1(3095,1385) ; R217.1@3115.31,4070 3160,4070 3170,4080 v1(3170,4090) ; R226.1@3345.31,4155 C213.1@3345.32,4230 3350,4234.69 v1(3350,4260) ; v1(3360,3925) 3360,3946.21 3351.21,3955 C500.1@3290,3955 3290,3918.79 3281.21,3910 3146.29,3910 3143.79,3907.5 3107.5,3907.5 U500.7@3105,3905 U500.2@2885,3905 ; v1(3365,2550) D401.K@3365,2624.69 ; R105.1@3375,1340.31 v1(3375,1380) ; v1@3490,1680 v1(3490.31,1680.31) R308.1@3490.31,1725 R307.1@3490.31,1875 R306.1@3490.31,2025
  Top Layer w30: C405.1@2200,3299.68 C404.2@2350,3299.68 ; v2(3515,1270) 3564.96,1270 C101.1@3569.96,1265 3569.96,1081.31 3537.6,1048.95 C100.2@3537.6,1040.03 ; v2(3590,1525) 3590.32,1524.68 C113.1@3640,1524.68 3707.6,1524.68 3730,1502.28 C110.2@3730,1493.43 3730,1457.57 3747.57,1440 4025.04,1440 4049.49,1464.45 VR101.1@4073.11,1464.45 4096.73,1464.45 4116.97,1484.68 C112.1@4175,1484.68 C111.1@4255,1484.68 4255,1457.57 4272.57,1440 4490,1440 4514.45,1464.45 VR100.1@4593.11,1464.45 4692.43,1464.45 4710.71,1482.73 4710.71,1526.38 4714.02,1529.68 C109.1@4715,1529.68 4792.13,1529.68 4811.81,1510 C108.1@4825,1510 ; v5(4020,995) C102.1@3955.32,995 3955.32,931.73 D101.2@3987.05,900 4067.32,900 D100.1@4107.32,940 ; U100.4@4520,1047.89 4575,1047.89 4600,1072.89 ; v2(4600,1050) 4600,1072.89 ; C106.1@4680,1098.66 4616.34,1098.66 4605,1110 4605,1194.69 R102.1@4600,1199.69 4600,1072.89
  Top Layer w50: C106.1@4680,1098.66 C107.1@4795,1098.66 5027.35,1098.66 5036.48,1107.8 C105.2@5040,1107.8 ; C303.2@5280,1435 5570,1435 5620,1485 C302.2@5620,1531.34
  Top Layer w100: D103.1@5175,2227.01 v1(5175,2685) 5365,2875 J302.4@5465,2875 ; C301.2@5200,4515 5550,4515 5580,4485 C300.2@5580,4470
  Bottom Layer w10: v1(2545,3975) 2645,3975 2654.36,3984.36 2654.36,4004.36 v1(2655.31,4005.31)
  Bottom Layer w15: v1(2179.68,4455.31) 2180,4455 v1(2180,4320) ; v1(2179.68,4624.69) 2399.68,4624.69 2410,4635 v1(2410,4650) ; v1(2280.31,4030.31) 2646.53,4030.31 2655.31,4021.53 v1(2655.31,4005.31) ; v1(2995,4275) v1(2995,4465) ; T102.1@3320,1035 3322.51,1037.51 3535.09,1037.51 C100.2@3537.6,1040.03
  Bottom Layer w30: C100.2@3537.6,1040.03 3537.6,959.97 3547.57,950 4002.43,950 4020,967.57 v5(4020,995) 4577.43,995 4595,1012.57 4595,1045 v2(4600,1050)
  Bottom Layer w50: C105.2@5040,1107.8 5040,1415 5060,1435 C303.2@5280,1435
  other v1: 3200,900 3300,900 3400,900 3200,975 3200,1050 3225,1475 3285,1475 3225,1525 3285,1525 3775,1775 3875,1775 3975,1775 4075,1775 4200,1775 4325,1775 3905,2060 3942.5,2060 3980,2060 4017.5,2060 4055,2060 3905,2093.75 3905,2127.5 3905,2161.25 2825,2175 2900,2175 3905,2195 3942.5,2195 3980,2195 4017.5,2195 4055,2195 2825,2225 2900,2225 5175,2450 5175,2525 5175,2600 2175,2750 5225,2750 2175,2800 5275,2800 3675,2825 2175,2850 2825,2875 2875,2875 2925,2875 2975,2875 3025,2875 2175,2900 2825,2925 2875,2925 2925,2925 2975,2925 3025,2925 3675,2925 2825,2975 2875,2975 2925,2975 2975,2975 3025,2975 2875,3025 2925,3025 2975,3025 3025,3025 3675,3025 3905,3035 3950,3035 3980,3035 4015,3035 4055,3035 2160,3055 3905,3075 2160,3110 3905,3110 3905,3140 2160,3155 3905,3170 3955,3170 3985,3170 4020,3170 4055,3170 2160,3205 3675,3400 3675,3500 3375,3630 3375,3670 3375,3720 3675,3825 3675,3925 3675,4000 3905,4000 3942.5,4000 3980,4000 4017.5,4000 4055,4000 3905,4035 3905,4070 3905,4105 3675,4130 3905,4140 3940,4140 3975,4140 4010,4140 4055,4140 3675,4180 2085,4185 3950,4650 4025,4650 4100,4650 4200,4650 4300,4650 5350,4650 5450,4650 4700,4700 4800,4700 4900,4700 5000,4700 5100,4700 5200,4700 5275,4700 5350,4700 5450,4700 2090,4715 2160,4715
  other v2: 2275,3299.68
